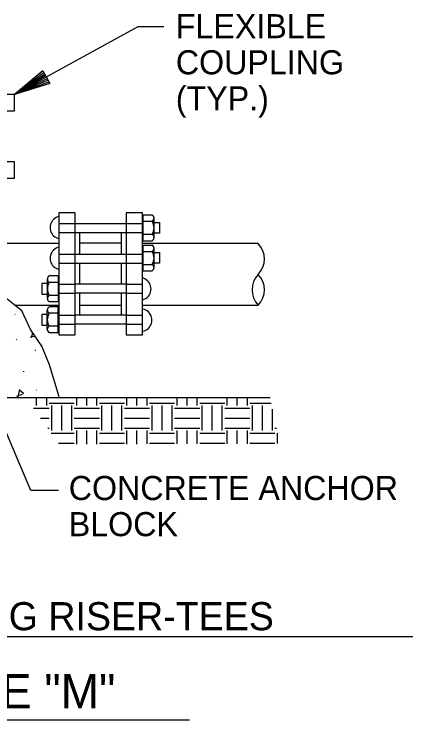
# Model space of a CAD drawing. Extents: x 9999.96 to 10005.26, y 9999.88 to 10002.38.
# Drawn here: x 10001.3787 to 10001.5442, y 10000.9494 to 10001.2424 of the extents above; entities that cross this region are included whole.
import ezdxf

# ---------------------------------------------------------------- set-up
doc = ezdxf.new("R2010")
doc.units = 0
doc.layers.add('Level 2', color=7, linetype='Continuous')

msp = doc.modelspace()

# ---------------------------------------------------------------- linework, layer by layer
at = {"layer": 'Level 2'}
for p, q in [((10001.39052, 10001.21884), (10001.37877, 10001.20897)), ((10001.37877, 10001.20897), (10001.3909, 10001.21818)), ((10001.39052, 10001.21884), (10001.39342, 10001.21356)), ((10001.37877, 10001.20897), (10001.39131, 10001.21745)), ((10001.37877, 10001.20897), (10001.39161, 10001.21685)), ((10001.39197, 10001.21624), (10001.37877, 10001.20897)), ((10001.37877, 10001.20897), (10001.39232, 10001.21557)), ((10001.37877, 10001.20897), (10001.39269, 10001.21493)), ((10001.37877, 10001.20897), (10001.39303, 10001.21428)), ((10001.39342, 10001.21356), (10001.37877, 10001.20897)), ((10001.43223, 10001.14829), (10001.43223, 10001.15903)), ((10001.43223, 10001.15903), (10001.43594, 10001.15903)), ((10001.43223, 10001.15635), (10001.43597, 10001.15635)), ((10001.43678, 10001.14965), (10001.43678, 10001.15769)), ((10001.39729, 10001.15545), (10001.40402, 10001.15545)), ((10001.404, 10001.15545), (10001.42523, 10001.15545)), ((10001.42523, 10001.15545), (10001.43196, 10001.15545)), ((10001.39729, 10001.15173), (10001.40402, 10001.15173)), ((10001.404, 10001.15173), (10001.42523, 10001.15173)), ((10001.40579, 10001.15173), (10001.40579, 10001.14275)), ((10001.42321, 10001.14275), (10001.42321, 10001.15173)), ((10001.42523, 10001.15173), (10001.43196, 10001.15173)), ((10001.43223, 10001.15096), (10001.43597, 10001.15096)), ((10001.43223, 10001.14829), (10001.43597, 10001.14829)), ((10001.36619, 10001.14723), (10001.39727, 10001.14723)), ((10001.4232, 10001.14725), (10001.40585, 10001.14725)), ((10001.43196, 10001.14723), (10001.48004, 10001.14723)), ((10001.43223, 10001.13578), (10001.43223, 10001.14652)), ((10001.43223, 10001.14652), (10001.43594, 10001.14652)), ((10001.43678, 10001.13714), (10001.43678, 10001.14518)), ((10001.39729, 10001.14272), (10001.40402, 10001.14272)), ((10001.404, 10001.14272), (10001.42523, 10001.14272)), ((10001.42523, 10001.14272), (10001.43196, 10001.14272)), ((10001.43223, 10001.14384), (10001.43597, 10001.14384)), ((10001.39729, 10001.139), (10001.40402, 10001.139)), ((10001.404, 10001.139), (10001.42523, 10001.139)), ((10001.40579, 10001.13901), (10001.40579, 10001.1303)), ((10001.42321, 10001.1303), (10001.42321, 10001.13901)), ((10001.42523, 10001.139), (10001.43196, 10001.139)), ((10001.43223, 10001.13845), (10001.43597, 10001.13845)), ((10001.43223, 10001.13578), (10001.43597, 10001.13578)), ((10001.39703, 10001.13369), (10001.39332, 10001.13369)), ((10001.39703, 10001.12295), (10001.39703, 10001.13369)), ((10001.39248, 10001.1243), (10001.39248, 10001.13234)), ((10001.39703, 10001.13101), (10001.39329, 10001.13101)), ((10001.39729, 10001.13031), (10001.40402, 10001.13031)), ((10001.42523, 10001.13031), (10001.404, 10001.13031)), ((10001.42523, 10001.13031), (10001.43196, 10001.13031)), ((10001.39703, 10001.12561), (10001.39329, 10001.12561)), ((10001.39729, 10001.12659), (10001.40402, 10001.12659)), ((10001.42523, 10001.12659), (10001.404, 10001.12659)), ((10001.40579, 10001.12656), (10001.40579, 10001.11734)), ((10001.42321, 10001.11734), (10001.42321, 10001.12656)), ((10001.42523, 10001.12659), (10001.43196, 10001.12659)), ((10001.37876, 10001.12161), (10001.39727, 10001.12161)), ((10001.39703, 10001.12295), (10001.39329, 10001.12295)), ((10001.40585, 10001.12161), (10001.4232, 10001.12161)), ((10001.43196, 10001.1216), (10001.48004, 10001.1216)), ((10001.39241, 10001.11148), (10001.39241, 10001.11952)), ((10001.39696, 10001.11819), (10001.39322, 10001.11819)), ((10001.39696, 10001.12086), (10001.39325, 10001.12086)), ((10001.39696, 10001.11013), (10001.39696, 10001.12086)), ((10001.37911, 10001.11767), (10001.37896, 10001.1178)), ((10001.39729, 10001.11734), (10001.40402, 10001.11734)), ((10001.42523, 10001.11734), (10001.404, 10001.11734)), ((10001.42523, 10001.11734), (10001.43196, 10001.11734)), ((10001.39696, 10001.11279), (10001.39322, 10001.11279)), ((10001.39729, 10001.11363), (10001.40402, 10001.11363)), ((10001.42523, 10001.11363), (10001.404, 10001.11363)), ((10001.42523, 10001.11363), (10001.43196, 10001.11363)), ((10001.38625, 10001.10986), (10001.3858, 10001.10792)), ((10001.39696, 10001.11013), (10001.39322, 10001.11013)), ((10001.3797, 10001.10719), (10001.37975, 10001.1074)), ((10001.38541, 10001.10822), (10001.38699, 10001.1087)), ((10001.3875, 10001.10281), (10001.3873, 10001.10275)), ((10001.38261, 10001.09411), (10001.38256, 10001.09392)), ((10001.38074, 10001.086), (10001.38018, 10001.08356)), ((10001.38263, 10001.08477), (10001.38079, 10001.08647)), ((10001.38776, 10001.08628), (10001.388, 10001.08635)), ((10001.2328, 10001.08318), (10001.48491, 10001.08318)), ((10001.37979, 10001.08384), (10001.38218, 10001.08457)), ((10001.38384, 10001.08291), (10001.38384, 10001.08331)), ((10001.38801, 10001.07989), (10001.38801, 10001.08331)), ((10001.39218, 10001.07989), (10001.39218, 10001.08331)), ((10001.40468, 10001.07989), (10001.40468, 10001.08331)), ((10001.40884, 10001.07989), (10001.40884, 10001.08331)), ((10001.41301, 10001.07989), (10001.41301, 10001.08331)), ((10001.42551, 10001.07989), (10001.42551, 10001.08331)), ((10001.42968, 10001.07989), (10001.42968, 10001.08331)), ((10001.43384, 10001.07989), (10001.43384, 10001.08331)), ((10001.44634, 10001.07989), (10001.44634, 10001.08331)), ((10001.45051, 10001.07989), (10001.45051, 10001.08331)), ((10001.45468, 10001.07989), (10001.45468, 10001.08331)), ((10001.46718, 10001.07989), (10001.46718, 10001.08331)), ((10001.47134, 10001.07989), (10001.47134, 10001.08331)), ((10001.47551, 10001.07989), (10001.47551, 10001.08331)), ((10001.39322, 10001.08093), (10001.40364, 10001.08093)), ((10001.41405, 10001.08093), (10001.42447, 10001.08093)), ((10001.43489, 10001.08093), (10001.4453, 10001.08093)), ((10001.45572, 10001.08093), (10001.46614, 10001.08093)), ((10001.47655, 10001.08093), (10001.48539, 10001.08093)), ((10001.38673, 10001.07884), (10001.39322, 10001.07884)), ((10001.39426, 10001.06947), (10001.39426, 10001.07989)), ((10001.39843, 10001.06947), (10001.39843, 10001.07989)), ((10001.40259, 10001.06947), (10001.40259, 10001.07989)), ((10001.40364, 10001.07884), (10001.41405, 10001.07884)), ((10001.41509, 10001.06947), (10001.41509, 10001.07989)), ((10001.41926, 10001.06947), (10001.41926, 10001.07989)), ((10001.42343, 10001.06947), (10001.42343, 10001.07989)), ((10001.42447, 10001.07884), (10001.43489, 10001.07884)), ((10001.43593, 10001.06947), (10001.43593, 10001.07989)), ((10001.44009, 10001.06947), (10001.44009, 10001.07989)), ((10001.44426, 10001.06947), (10001.44426, 10001.07989)), ((10001.4453, 10001.07884), (10001.45572, 10001.07884)), ((10001.45676, 10001.06947), (10001.45676, 10001.07989)), ((10001.46093, 10001.06947), (10001.46093, 10001.07989)), ((10001.46509, 10001.06947), (10001.46509, 10001.07989)), ((10001.46614, 10001.07884), (10001.47655, 10001.07884)), ((10001.47759, 10001.06947), (10001.47759, 10001.07989)), ((10001.48176, 10001.06947), (10001.48176, 10001.07989)), ((10001.48593, 10001.06947), (10001.48593, 10001.07834)), ((10001.38968, 10001.07468), (10001.39322, 10001.07468)), ((10001.40364, 10001.07468), (10001.41405, 10001.07468)), ((10001.42447, 10001.07468), (10001.43489, 10001.07468)), ((10001.4453, 10001.07468), (10001.45572, 10001.07468)), ((10001.46614, 10001.07468), (10001.47655, 10001.07468)), ((10001.39263, 10001.07051), (10001.39322, 10001.07051)), ((10001.3941, 10001.06843), (10001.40364, 10001.06843)), ((10001.40364, 10001.07051), (10001.41405, 10001.07051)), ((10001.40468, 10001.06382), (10001.40468, 10001.06947)), ((10001.40884, 10001.06383), (10001.40884, 10001.06947)), ((10001.41301, 10001.06385), (10001.41301, 10001.06947)), ((10001.41405, 10001.06843), (10001.42447, 10001.06843)), ((10001.42447, 10001.07051), (10001.43489, 10001.07051)), ((10001.42551, 10001.06389), (10001.42551, 10001.06947)), ((10001.42968, 10001.0639), (10001.42968, 10001.06947)), ((10001.43384, 10001.06392), (10001.43384, 10001.06947)), ((10001.43489, 10001.06843), (10001.4453, 10001.06843)), ((10001.4453, 10001.07051), (10001.45572, 10001.07051)), ((10001.44634, 10001.06395), (10001.44634, 10001.06947)), ((10001.45051, 10001.06396), (10001.45051, 10001.06947)), ((10001.45468, 10001.06398), (10001.45468, 10001.06947)), ((10001.45572, 10001.06843), (10001.46614, 10001.06843)), ((10001.46614, 10001.07051), (10001.47655, 10001.07051)), ((10001.46718, 10001.06401), (10001.46718, 10001.06947)), ((10001.47134, 10001.06402), (10001.47134, 10001.06947)), ((10001.47551, 10001.06404), (10001.47551, 10001.06947)), ((10001.47655, 10001.06843), (10001.48697, 10001.06843)), ((10001.48697, 10001.07051), (10001.48758, 10001.07051)), ((10001.48801, 10001.06407), (10001.48801, 10001.06848)), ((10001.39706, 10001.06426), (10001.40364, 10001.06426)), ((10001.41405, 10001.06426), (10001.42447, 10001.06426)), ((10001.43489, 10001.06426), (10001.4453, 10001.06426)), ((10001.45572, 10001.06426), (10001.46614, 10001.06426)), ((10001.47655, 10001.06426), (10001.48697, 10001.06426)), ((10001.20075, 10000.98401), (10001.54424, 10000.98401)), ((10001.30773, 10000.9494), (10001.45144, 10000.9494))]:
    msp.add_line(p, q, dxfattribs=at)
for points in [[(10001.44085, 10001.23715), (10001.43008, 10001.23715), (10001.37877, 10001.20897)], [(10001.39727, 10001.1583), (10001.39669, 10001.15815), (10001.3961, 10001.15789), (10001.39556, 10001.15756), (10001.39506, 10001.15716), (10001.39463, 10001.1567), (10001.39426, 10001.15618), (10001.39397, 10001.1556), (10001.39375, 10001.15501), (10001.39363, 10001.15439), (10001.39358, 10001.15375), (10001.39363, 10001.15311), (10001.39375, 10001.15249), (10001.39397, 10001.15189), (10001.39426, 10001.15132), (10001.39463, 10001.1508), (10001.39506, 10001.15034), (10001.39556, 10001.14994), (10001.3961, 10001.1496), (10001.39669, 10001.14935), (10001.39727, 10001.1492)], [(10001.4368, 10001.15588), (10001.43906, 10001.15588), (10001.43906, 10001.15147), (10001.4368, 10001.15147)], [(10001.39727, 10001.14557), (10001.39669, 10001.14542), (10001.3961, 10001.14516), (10001.39556, 10001.14483), (10001.39506, 10001.14443), (10001.39463, 10001.14397), (10001.39426, 10001.14345), (10001.39397, 10001.14288), (10001.39375, 10001.14228), (10001.39363, 10001.14166), (10001.39358, 10001.14102), (10001.39363, 10001.14039), (10001.39375, 10001.13976), (10001.39397, 10001.13916), (10001.39426, 10001.13859), (10001.39463, 10001.13807), (10001.39506, 10001.13761), (10001.39556, 10001.13721), (10001.3961, 10001.13688), (10001.39669, 10001.13663), (10001.39727, 10001.13647)], [(10001.4368, 10001.14336), (10001.43906, 10001.14336), (10001.43906, 10001.13896), (10001.4368, 10001.13896)], [(10001.43196, 10001.12377), (10001.43242, 10001.1239), (10001.433, 10001.12415), (10001.43355, 10001.12448), (10001.43404, 10001.12489), (10001.43448, 10001.12534), (10001.43484, 10001.12586), (10001.43514, 10001.12643), (10001.43535, 10001.12703), (10001.43548, 10001.12766), (10001.43553, 10001.12829), (10001.43548, 10001.12893), (10001.43535, 10001.12955), (10001.43514, 10001.13016), (10001.43484, 10001.13072), (10001.43448, 10001.13124), (10001.43404, 10001.1317), (10001.43355, 10001.1321), (10001.433, 10001.13243), (10001.43242, 10001.13269), (10001.43196, 10001.13281)], [(10001.39743, 10001.08351), (10001.39331, 10001.09677), (10001.3901, 10001.10455), (10001.38553, 10001.11142), (10001.38188, 10001.1192), (10001.37501, 10001.12469), (10001.36311, 10001.13109), (10001.35259, 10001.13109), (10001.34435, 10001.13154), (10001.33611, 10001.1288), (10001.32743, 10001.12469), (10001.32056, 10001.11645), (10001.31507, 10001.10684), (10001.3105, 10001.09723), (10001.30758, 10001.08318)], [(10001.39246, 10001.13053), (10001.3902, 10001.13053), (10001.3902, 10001.12613), (10001.39246, 10001.12613)], [(10001.43196, 10001.11071), (10001.43278, 10001.11093), (10001.43336, 10001.11118), (10001.43391, 10001.11151), (10001.43441, 10001.11192), (10001.43483, 10001.11238), (10001.43521, 10001.1129), (10001.4355, 10001.11346), (10001.43572, 10001.11406), (10001.43584, 10001.11469), (10001.43589, 10001.11532), (10001.43584, 10001.11596), (10001.43572, 10001.11658), (10001.4355, 10001.11718), (10001.43521, 10001.11775), (10001.43483, 10001.11827), (10001.43441, 10001.11873), (10001.43391, 10001.11914), (10001.43336, 10001.11946), (10001.43278, 10001.11972), (10001.43196, 10001.11994)], [(10001.39239, 10001.11771), (10001.39013, 10001.11771), (10001.39013, 10001.1133), (10001.39239, 10001.1133)], [(10001.39709, 10001.04459), (10001.38565, 10001.04459), (10001.36949, 10001.08229)]]:
    msp.add_lwpolyline(points, dxfattribs=at)
for points in [[(10001.3281, 10001.20224), (10001.37877, 10001.20224), (10001.37877, 10001.20897), (10001.3281, 10001.20897)], [(10001.3281, 10001.17428), (10001.37877, 10001.17428), (10001.37877, 10001.18101), (10001.3281, 10001.18101)], [(10001.39727, 10001.15988), (10001.39727, 10001.10921), (10001.404, 10001.10921), (10001.404, 10001.15988)], [(10001.42523, 10001.15988), (10001.42523, 10001.10921), (10001.43196, 10001.10921), (10001.43196, 10001.15988)]]:
    msp.add_lwpolyline(points, close=True, dxfattribs=at)
for centre, radius, start, end in [((10001.43527, 10001.15768), 0.0015, 298.1609, 63.2173), ((10001.43182, 10001.15365), 0.00496, 327.057, 32.9938), ((10001.43528, 10001.14963), 0.0015, 297.9658, 62.1123), ((10001.43527, 10001.14517), 0.0015, 298.1609, 63.2173), ((10001.47344, 10001.1407), 0.00918, 315.9775, 44.0212), ((10001.43182, 10001.14114), 0.00496, 327.057, 32.9938), ((10001.43528, 10001.13712), 0.0015, 297.9658, 62.1123), ((10001.39399, 10001.13234), 0.0015, 116.7827, 241.8391), ((10001.48664, 10001.12794), 0.00918, 135.9775, 224.0212), ((10001.47344, 10001.12794), 0.00918, 315.9788, 44.0225), ((10001.39744, 10001.12831), 0.00496, 147.0062, 212.943), ((10001.39398, 10001.12428), 0.0015, 117.8877, 242.0342), ((10001.39737, 10001.11549), 0.00496, 147.0062, 212.943), ((10001.39392, 10001.11952), 0.0015, 116.7827, 241.8391), ((10001.39391, 10001.11146), 0.0015, 117.8877, 242.0342)]:
    msp.add_arc(centre, radius, start, end, dxfattribs=at)

# ---------------------------------------------------------------- texts
for s, height, p in [('FLEXIBLE', 0.01, (10001.4458, 10001.23236)), ('COUPLING', 0.01, (10001.4458, 10001.21736)), ('(TYP.)', 0.01, (10001.4458, 10001.20236)), ('CONCRETE ANCHOR', 0.01, (10001.40135, 10001.04065)), ('BLOCK', 0.01, (10001.40135, 10001.02565)), ('UNDERGROUND PIPING RISER-TEES', 0.0116667, (10001.20653, 10000.9866)), ('FIGURE "M"', 0.014301, (10001.31366, 10000.95413))]:
    msp.add_text(s, height=height, dxfattribs=at).set_placement(p)

doc.saveas('drawing.dxf')
